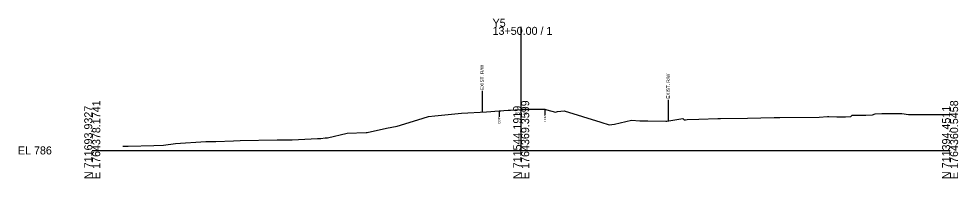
# Model space of a CAD drawing. Extents: x -26 to 303, y -10 to 4039.
# Drawn here: x -25.7 to 302.8, y 3490.3 to 3546 of the extents above; entities that cross this region are included whole.
import ezdxf

# ---------------------------------------------------------------- set-up
doc = ezdxf.new("R2010")
doc.units = 0
for name, color, linetype in [('Default', 7, 'Continuous'), ('Exist Cross Section Cell', 7, 'Continuous'), ('Exist XS Center Line Elevation Label', 7, 'Continuous'), ('Exist XS Ground Line', 7, 'Continuous'), ('Old_Level_10', 7, 'Continuous')]:
    doc.layers.add(name, color=color, linetype=linetype)

msp = doc.modelspace()

# ---------------------------------------------------------------- linework, layer by layer
at = {"layer": 'Exist Cross Section Cell'}
for p, q in [((150, 3500), (150, 3543.15)), ((0, 3500), (150, 3500)), ((150, 3500), (300, 3500))]:
    msp.add_line(p, q, dxfattribs=at)
at = {"layer": 'Exist XS Ground Line'}
msp.add_lwpolyline([(10.69, 3501.45), (11.52, 3501.49), (12.61, 3501.54), (21.59, 3501.74), (24.88, 3501.84), (29.11, 3502.44), (39.72, 3503.1), (41.58, 3503.11), (43.2, 3503.11), (49.44, 3503.4), (51.68, 3503.51), (64.66, 3503.64), (66.1, 3503.65), (66.81, 3503.65), (69.89, 3503.71), (78.77, 3504.15), (79.95, 3504.18), (81.5, 3504.34), (82.25, 3504.41), (89.13, 3506.01), (95.82, 3506.22), (96.13, 3506.27), (102.93, 3507.77), (106.65, 3508.48), (113.87, 3510.64), (117.62, 3511.89), (119.86, 3512.1), (129.12, 3512.96), (137.93, 3513.48), (142.27, 3513.79), (142.6, 3513.84), (142.93, 3513.87), (143.9, 3513.94), (145.43, 3514.05), (146.26, 3514.11), (147.94, 3514.22), (150, 3514.33), (150.44, 3514.36), (152.48, 3514.38), (152.95, 3514.38), (155.14, 3514.37), (155.85, 3514.37), (157.23, 3514.38), (157.65, 3514.37), (158.33, 3514.36), (158.96, 3514.13), (161.98, 3513.39), (162.72, 3513.57), (165.09, 3513.81), (177.9, 3509.88), (180.8, 3508.89), (182.58, 3509.22), (188.56, 3510.58), (191.5, 3510.36), (192.76, 3510.35), (194.27, 3510.31), (200.54, 3510.17), (200.93, 3510.24), (206.53, 3511.2), (207.03, 3510.7), (207.41, 3510.73), (208.03, 3510.76), (212.09, 3510.91), (218.73, 3511.15), (219.73, 3511.15), (229.19, 3511.29), (238.5, 3511.51), (240.46, 3511.55), (254.2, 3511.63), (257.12, 3511.79), (257.62, 3511.79), (260.37, 3511.78), (263.48, 3511.73), (265.3, 3511.81), (265.8, 3512.33), (266.45, 3512.35), (270.57, 3512.27), (272.89, 3512.46), (273.83, 3512.8), (276.13, 3512.92), (278.31, 3512.9), (281.05, 3512.88), (282.43, 3512.91), (283.13, 3512.92), (285.42, 3512.54), (286.97, 3512.49), (290.9, 3512.5), (296.34, 3512.54), (300, 3512.54)], dxfattribs=at)
at = {"layer": 'Old_Level_10'}
for p, q in [((136.34, 3520.78), (136.34, 3513.38)), ((201.4, 3517.72), (201.4, 3510.32)), ((142.27, 3513.79), (142.27, 3511.74)), ((158.33, 3514.36), (158.33, 3512.3))]:
    msp.add_line(p, q, dxfattribs=at)

# ---------------------------------------------------------------- texts
at = {"layer": 'Default'}
msp.add_text('-', height=0.0001, dxfattribs=at).set_placement((0, 3500))
at = {"layer": 'Exist Cross Section Cell'}
for s, p in [('Y5', (140, 3543.15)), ('13+50.00 / 1', (140, 3540.35)), ('EL 786', (-26, 3498.6))]:
    msp.add_text(s, height=2.8, dxfattribs=at).set_placement(p)
for s, p in [('N 711693.9327', (0, 3490)), ('E 1764378.1741', (2.8, 3490)), ('N 711544.1919', (150, 3490)), ('E 1764369.3599', (152.8, 3490)), ('N 711394.4511', (300, 3490)), ('E 1764360.5458', (302.8, 3490))]:
    msp.add_text(s, height=2.8, rotation=90, dxfattribs=at).set_placement(p)
at = {"layer": 'Exist XS Center Line Elevation Label'}
msp.add_text('800.33', height=1, dxfattribs=at).set_placement((147.88, 3512.33))
at = {"layer": 'Old_Level_10'}
for s, height, p in [('EXIST. R/W', 1.181, (136.93, 3521.09)), ('EXIST. R/W', 1.181, (201.99, 3518.02)), ('EOP', 0.787, (158.73, 3509.91)), ('EOP', 0.787, (142.66, 3509.34))]:
    msp.add_text(s, height=height, rotation=90, dxfattribs=at).set_placement(p)

doc.saveas('drawing.dxf')
